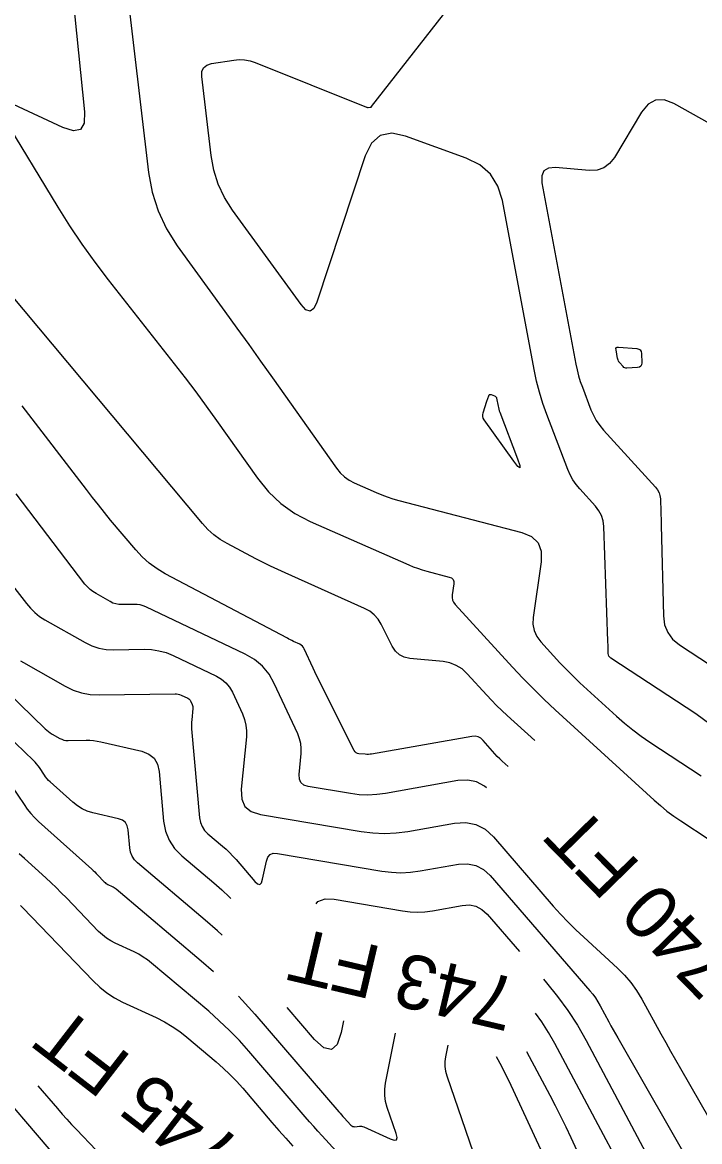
# Model space of a CAD drawing. Extents: x 1354696 to 1366163, y 660729 to 670380.
# Drawn here: x 1361392.2 to 1361467.7, y 664438.2 to 664563.1 of the extents above; entities that cross this region are included whole.
import ezdxf

# ---------------------------------------------------------------- set-up
doc = ezdxf.new("R2010")
doc.units = 0
doc.layers.add('R_Contour Annot', color=7, linetype='Continuous')
doc.layers.add('R_Contours', color=7, linetype='Continuous')

msp = doc.modelspace()

# ---------------------------------------------------------------- linework, layer by layer
at = {"layer": 'R_Contours'}
for points in [[(1361402.78, 664576.02), (1361406.27, 664546.35), (1361406.67, 664544.15), (1361407.34, 664542.05), (1361408.27, 664540.06), (1361409.47, 664538.17), (1361414.8, 664530.82), (1361416.13, 664528.98), (1361417.46, 664527.14), (1361418.77, 664525.29), (1361420.09, 664523.44), (1361427.23, 664513.33), (1361427.65, 664512.82), (1361428.12, 664512.38), (1361428.64, 664512), (1361429.22, 664511.7), (1361431.66, 664510.62), (1361432.27, 664510.37), (1361432.9, 664510.14), (1361433.53, 664509.93), (1361434.17, 664509.75), (1361447.91, 664506.17), (1361448.99, 664505.71), (1361449.72, 664505.02), (1361450.07, 664504.09), (1361450.07, 664502.91), (1361449.18, 664496.69), (1361449.14, 664495.93), (1361449.27, 664495.22), (1361449.57, 664494.57), (1361450.02, 664493.96), (1361452.15, 664491.63), (1361452.69, 664491.05), (1361453.24, 664490.49), (1361453.81, 664489.94), (1361454.38, 664489.4), (1361458.45, 664485.67), (1361459.34, 664484.89), (1361460.26, 664484.15), (1361461.2, 664483.45), (1361462.18, 664482.78), (1361467.9, 664479.01)], [(1361397.16, 664572.51), (1361399.15, 664553.09), (1361399.11, 664551.85), (1361398.69, 664551.15), (1361397.89, 664550.99), (1361396.71, 664551.36), (1361391.22, 664553.92)], [(1361468.87, 664484.79), (1361467.31, 664485.92), (1361457.82, 664492.16), (1361457.7, 664492.26), (1361457.61, 664492.38), (1361457.55, 664492.53), (1361457.53, 664492.68), (1361457.52, 664493.36), (1361457.51, 664493.53), (1361457.51, 664493.7), (1361457.5, 664493.87), (1361457.49, 664494.04), (1361457.03, 664506.84), (1361456.96, 664507.47), (1361456.78, 664508.05), (1361456.5, 664508.6), (1361456.11, 664509.1), (1361454.35, 664511.03), (1361453.94, 664511.52), (1361453.58, 664512.05), (1361453.27, 664512.61), (1361453.01, 664513.2), (1361450.68, 664519.33), (1361450.24, 664520.56), (1361449.86, 664521.81), (1361449.53, 664523.07), (1361449.26, 664524.35), (1361445.74, 664543.2), (1361445.24, 664544.82), (1361444.4, 664546.15), (1361443.22, 664547.2), (1361441.7, 664547.95), (1361434.94, 664550.39), (1361433.39, 664550.71), (1361432.12, 664550.46), (1361431.14, 664549.62), (1361430.43, 664548.2), (1361425.04, 664531.87), (1361424.7, 664531.16), (1361424.29, 664530.88), (1361423.82, 664531.02), (1361423.28, 664531.6), (1361415.63, 664542.14), (1361414.74, 664543.55), (1361414.04, 664545.03), (1361413.55, 664546.59), (1361413.25, 664548.23), (1361412.21, 664557.05), (1361412.23, 664557.6), (1361412.41, 664558.03), (1361412.77, 664558.32), (1361413.3, 664558.49), (1361415.78, 664558.88), (1361416.39, 664558.93), (1361416.99, 664558.91), (1361417.59, 664558.8), (1361418.17, 664558.6), (1361430.59, 664553.62), (1361430.63, 664553.61), (1361430.68, 664553.6), (1361430.73, 664553.59), (1361430.78, 664553.59), (1361430.99, 664553.61), (1361431.04, 664553.62), (1361431.08, 664553.64), (1361431.12, 664553.67), (1361431.15, 664553.7), (1361440.49, 664565.72)], [(1361483.26, 664543.73), (1361464.84, 664554.02), (1361463.77, 664554.44), (1361462.82, 664554.42), (1361461.98, 664553.96), (1361461.26, 664553.07), (1361458.23, 664548.02), (1361457.69, 664547.33), (1361457.04, 664546.85), (1361456.28, 664546.6), (1361455.4, 664546.57), (1361451.66, 664546.88), (1361450.87, 664546.83), (1361450.35, 664546.53), (1361450.11, 664545.98), (1361450.14, 664545.19), (1361453.92, 664524.96), (1361454.06, 664524.31), (1361454.23, 664523.65), (1361454.42, 664523.01), (1361454.65, 664522.38), (1361455.61, 664519.85), (1361455.88, 664519.24), (1361456.2, 664518.66), (1361456.58, 664518.11), (1361457, 664517.59), (1361462.82, 664511.21), (1361463.04, 664510.92), (1361463.2, 664510.61), (1361463.3, 664510.28), (1361463.35, 664509.93), (1361463.4, 664508.45), (1361463.41, 664508.09), (1361463.42, 664507.72), (1361463.44, 664507.35), (1361463.45, 664506.98), (1361463.69, 664496.85), (1361463.82, 664495.88), (1361464.16, 664495.02), (1361464.71, 664494.27), (1361465.47, 664493.65), (1361468.93, 664491.37)], [(1361390.04, 664552.6), (1361396.15, 664542.48), (1361397.46, 664540.38), (1361398.83, 664538.33), (1361400.27, 664536.32), (1361401.77, 664534.36), (1361409.14, 664525), (1361410.35, 664523.44), (1361411.54, 664521.86), (1361412.71, 664520.27), (1361413.86, 664518.67), (1361418.42, 664512.22), (1361419.64, 664510.71), (1361421.03, 664509.4), (1361422.59, 664508.3), (1361424.31, 664507.4), (1361435.28, 664502.56), (1361435.77, 664502.35), (1361436.27, 664502.17), (1361436.78, 664502), (1361437.29, 664501.85), (1361439.8, 664501.2), (1361440.06, 664501.09), (1361440.23, 664500.93), (1361440.31, 664500.71), (1361440.31, 664500.43), (1361440.13, 664499.21), (1361440.12, 664498.91), (1361440.17, 664498.63), (1361440.29, 664498.38), (1361440.46, 664498.14), (1361446.87, 664491.14), (1361448.02, 664489.91), (1361449.2, 664488.71), (1361450.4, 664487.53), (1361451.63, 664486.38), (1361462.64, 664476.31), (1361463.35, 664475.69), (1361464.08, 664475.09), (1361464.84, 664474.53), (1361465.62, 664473.99), (1361468.78, 664471.91)], [(1361449.34, 664482.94), (1361446.26, 664485.76), (1361445.67, 664486.31), (1361445.09, 664486.87), (1361444.53, 664487.45), (1361443.98, 664488.03), (1361441.81, 664490.41), (1361441.23, 664490.94), (1361440.59, 664491.34), (1361439.88, 664491.61), (1361439.11, 664491.76), (1361435.42, 664492.12), (1361434.79, 664492.25), (1361434.25, 664492.52), (1361433.8, 664492.93), (1361433.45, 664493.47), (1361432.22, 664495.92), (1361431.87, 664496.49), (1361431.45, 664496.97), (1361430.94, 664497.38), (1361430.36, 664497.7), (1361421.51, 664501.65), (1361420.68, 664502.02), (1361419.87, 664502.41), (1361419.05, 664502.82), (1361418.25, 664503.23), (1361415.05, 664504.93), (1361414.27, 664505.38), (1361413.55, 664505.91), (1361412.89, 664506.5), (1361412.28, 664507.16), (1361390.61, 664533.09)], [(1361446.38, 664480.04), (1361445.72, 664480.65), (1361445.43, 664480.92), (1361445.15, 664481.19), (1361444.89, 664481.48), (1361444.62, 664481.77), (1361443.6, 664482.96), (1361443.32, 664483.21), (1361443.02, 664483.37), (1361442.68, 664483.44), (1361442.31, 664483.42), (1361431.14, 664481.44), (1361430.97, 664481.42), (1361430.79, 664481.41), (1361430.62, 664481.4), (1361430.44, 664481.42), (1361429.73, 664481.48), (1361429.57, 664481.52), (1361429.43, 664481.59), (1361429.31, 664481.69), (1361429.22, 664481.84), (1361425.43, 664489.39), (1361425.22, 664489.8), (1361425.02, 664490.21), (1361424.83, 664490.62), (1361424.63, 664491.04), (1361423.64, 664493.18), (1361423.55, 664493.34), (1361423.43, 664493.48), (1361423.29, 664493.6), (1361423.13, 664493.69), (1361422.44, 664494.02), (1361422.27, 664494.1), (1361422.1, 664494.19), (1361421.93, 664494.27), (1361421.76, 664494.36), (1361408.14, 664501.56), (1361407.22, 664502.1), (1361406.36, 664502.73), (1361405.56, 664503.44), (1361404.84, 664504.23), (1361402.05, 664507.56), (1361401.36, 664508.4), (1361400.68, 664509.24), (1361400.01, 664510.09), (1361399.34, 664510.95), (1361392.19, 664520.29)], [(1361443.97, 664477.67), (1361443.75, 664477.87), (1361442.85, 664478.34), (1361441.86, 664478.54), (1361440.77, 664478.48), (1361432.69, 664477.05), (1361431.72, 664476.92), (1361430.74, 664476.87), (1361429.77, 664476.91), (1361428.79, 664477.04), (1361424.09, 664477.83), (1361423.6, 664477.99), (1361423.27, 664478.27), (1361423.09, 664478.66), (1361423.06, 664479.18), (1361423.29, 664481.49), (1361423.31, 664482.06), (1361423.25, 664482.61), (1361423.12, 664483.16), (1361422.91, 664483.69), (1361420.3, 664489.32), (1361419.71, 664490.36), (1361418.97, 664491.25), (1361418.09, 664492), (1361417.05, 664492.6), (1361405.98, 664497.86), (1361405.66, 664497.99), (1361405.34, 664498.08), (1361405.01, 664498.13), (1361404.67, 664498.14), (1361403.29, 664498.12), (1361402.95, 664498.14), (1361402.63, 664498.2), (1361402.31, 664498.3), (1361402.01, 664498.45), (1361400.43, 664499.35), (1361400.08, 664499.57), (1361399.75, 664499.82), (1361399.46, 664500.11), (1361399.19, 664500.42), (1361391.5, 664510.47)], [(1361390.6, 664500.92), (1361392.65, 664498.25), (1361393.1, 664497.72), (1361393.59, 664497.24), (1361394.13, 664496.81), (1361394.72, 664496.44), (1361399.2, 664493.89), (1361399.95, 664493.53), (1361400.73, 664493.27), (1361401.54, 664493.12), (1361402.37, 664493.08), (1361405.77, 664493.14), (1361406.61, 664493.11), (1361407.43, 664492.98), (1361408.23, 664492.76), (1361409.01, 664492.44), (1361413.85, 664490.14), (1361414.42, 664489.81), (1361414.9, 664489.4), (1361415.3, 664488.91), (1361415.63, 664488.35), (1361416.75, 664485.92), (1361416.99, 664485.3), (1361417.14, 664484.67), (1361417.21, 664484.03), (1361417.19, 664483.37), (1361416.61, 664477.51), (1361416.66, 664476.43), (1361417.03, 664475.61), (1361417.73, 664475.03), (1361418.76, 664474.71), (1361429.98, 664472.8), (1361431.28, 664472.64), (1361432.58, 664472.59), (1361433.89, 664472.65), (1361435.19, 664472.82), (1361440.4, 664473.74), (1361441.65, 664473.82), (1361442.78, 664473.59), (1361443.81, 664473.05), (1361444.73, 664472.2), (1361451.4, 664464.49), (1361452.21, 664463.58), (1361453.05, 664462.69), (1361453.91, 664461.83), (1361454.8, 664461), (1361458.57, 664457.55), (1361459.35, 664456.78), (1361460.06, 664455.94), (1361460.7, 664455.06), (1361461.27, 664454.11), (1361463.41, 664450.22), (1361463.95, 664449.25), (1361464.49, 664448.28), (1361465.04, 664447.32), (1361465.59, 664446.35), (1361472.04, 664435.11)], [(1361392, 664491.85), (1361392.32, 664491.66), (1361396.97, 664489.01), (1361397.88, 664488.57), (1361398.81, 664488.26), (1361399.78, 664488.08), (1361400.78, 664488.04), (1361409.23, 664488.18), (1361409.41, 664488.17), (1361409.58, 664488.14), (1361409.74, 664488.1), (1361409.9, 664488.03), (1361410.65, 664487.67), (1361410.75, 664487.62), (1361410.83, 664487.55), (1361410.9, 664487.47), (1361410.95, 664487.38), (1361411.14, 664486.97), (1361411.18, 664486.87), (1361411.2, 664486.76), (1361411.21, 664486.65), (1361411.21, 664486.54), (1361411.09, 664485.26), (1361411.07, 664485.01), (1361411.06, 664484.76), (1361411.06, 664484.51), (1361411.08, 664484.26), (1361411.96, 664474.33), (1361412.06, 664473.82), (1361412.24, 664473.35), (1361412.52, 664472.93), (1361412.88, 664472.56), (1361414.52, 664471.18), (1361414.92, 664470.82), (1361415.31, 664470.45), (1361415.68, 664470.07), (1361416.04, 664469.67), (1361418.12, 664467.24), (1361418.43, 664466.96), (1361418.68, 664466.9), (1361418.87, 664467.07), (1361419, 664467.47), (1361419.41, 664469.51), (1361419.56, 664469.94), (1361419.82, 664470.23), (1361420.18, 664470.37), (1361420.64, 664470.36), (1361432.29, 664468.38), (1361433.36, 664468.25), (1361434.42, 664468.2), (1361435.49, 664468.25), (1361436.56, 664468.4), (1361440.83, 664469.15), (1361441.85, 664469.21), (1361442.78, 664469.02), (1361443.63, 664468.58), (1361444.38, 664467.89), (1361455.49, 664455.03), (1361455.82, 664454.64), (1361456.11, 664454.23), (1361456.39, 664453.8), (1361456.64, 664453.36), (1361457.6, 664451.56), (1361457.84, 664451.11), (1361458.08, 664450.66), (1361458.33, 664450.22), (1361458.59, 664449.78), (1361467.26, 664434.66)], [(1361389.1, 664489.71), (1361394.75, 664484.26), (1361394.93, 664484.1), (1361395.12, 664483.95), (1361395.32, 664483.81), (1361395.53, 664483.68), (1361396.38, 664483.19), (1361396.6, 664483.09), (1361396.83, 664483.01), (1361397.06, 664482.97), (1361397.31, 664482.96), (1361399.31, 664482.99), (1361399.72, 664482.98), (1361400.13, 664482.95), (1361400.54, 664482.9), (1361400.95, 664482.81), (1361405.51, 664481.75), (1361406.31, 664481.45), (1361406.9, 664480.97), (1361407.28, 664480.32), (1361407.47, 664479.49), (1361407.96, 664473.95), (1361408.16, 664472.83), (1361408.57, 664471.82), (1361409.17, 664470.9), (1361409.97, 664470.09), (1361413.56, 664467.06), (1361414.44, 664466.28), (1361415.29, 664465.47), (1361415.44, 664465.32)], [(1361414.48, 664461.24), (1361413.96, 664461.73), (1361412.59, 664462.93), (1361405.05, 664469.31), (1361404.71, 664469.66), (1361404.45, 664470.05), (1361404.28, 664470.49), (1361404.19, 664470.97), (1361404.01, 664472.99), (1361403.91, 664473.45), (1361403.69, 664473.8), (1361403.37, 664474.07), (1361402.93, 664474.23), (1361400.06, 664474.9), (1361399.45, 664475.09), (1361398.87, 664475.34), (1361398.34, 664475.67), (1361397.83, 664476.07), (1361395.32, 664478.33), (1361395.13, 664478.51), (1361394.96, 664478.69), (1361394.8, 664478.89), (1361394.66, 664479.1), (1361394.1, 664479.95), (1361393.95, 664480.15), (1361393.79, 664480.35), (1361393.63, 664480.54), (1361393.45, 664480.73), (1361388.41, 664485.58)], [(1361391.01, 664477.91), (1361392.4, 664475.81), (1361392.76, 664475.3), (1361393.15, 664474.81), (1361393.57, 664474.35), (1361394.02, 664473.92), (1361399.94, 664468.59), (1361400.11, 664468.44), (1361400.27, 664468.29), (1361400.43, 664468.13), (1361400.59, 664467.97), (1361401.33, 664467.19), (1361401.43, 664467.1), (1361401.53, 664467.02), (1361401.64, 664466.95), (1361401.75, 664466.89), (1361402.22, 664466.67), (1361402.34, 664466.62), (1361402.45, 664466.55), (1361402.56, 664466.48), (1361402.66, 664466.4), (1361412.15, 664458.37), (1361413.52, 664457.17)], [(1361427.98, 664436.3), (1361425.64, 664438.83), (1361425.16, 664439.36), (1361424.69, 664439.88), (1361424.22, 664440.41), (1361423.75, 664440.95), (1361417.46, 664448.29), (1361416.4, 664449.47), (1361415.31, 664450.6), (1361414.16, 664451.69), (1361412.98, 664452.74), (1361406.61, 664458.12), (1361406.16, 664458.48), (1361405.68, 664458.8), (1361405.19, 664459.1), (1361404.67, 664459.36), (1361402.57, 664460.34), (1361402.06, 664460.6), (1361401.58, 664460.91), (1361401.13, 664461.27), (1361400.71, 664461.66), (1361397.11, 664465.41), (1361396.55, 664465.98), (1361395.98, 664466.54), (1361395.4, 664467.09), (1361394.81, 664467.64), (1361392.43, 664469.78), (1361391.86, 664470.33)], [(1361392, 664464.55), (1361392.27, 664464.27), (1361400.09, 664456.13), (1361400.83, 664455.43), (1361401.63, 664454.8), (1361402.48, 664454.25), (1361403.39, 664453.78), (1361407.12, 664452.04), (1361408.04, 664451.58), (1361408.91, 664451.06), (1361409.75, 664450.48), (1361410.56, 664449.84), (1361413.8, 664447.1), (1361414.59, 664446.41), (1361415.35, 664445.68), (1361416.08, 664444.93), (1361416.78, 664444.15), (1361420.03, 664440.35), (1361420.81, 664439.46), (1361421.59, 664438.57), (1361422.38, 664437.69)], [(1361424.95, 664464.74), (1361425.17, 664464.98), (1361425.96, 664465.28), (1361426.97, 664465.25), (1361434.6, 664463.96), (1361435.43, 664463.85), (1361436.27, 664463.82), (1361437.1, 664463.86), (1361437.93, 664463.97), (1361441.26, 664464.56), (1361442.06, 664464.61), (1361442.78, 664464.46), (1361443.44, 664464.12), (1361444.03, 664463.58), (1361447.64, 664459.4)], [(1361450.3, 664456.32), (1361450.64, 664455.93), (1361451.88, 664454.41), (1361453.03, 664452.83), (1361454.09, 664451.18), (1361455.06, 664449.48), (1361464.27, 664432.19)], [(1361416.3, 664454.44), (1361416.73, 664454), (1361418.14, 664452.43), (1361427.48, 664441.53), (1361427.63, 664441.36), (1361427.78, 664441.19), (1361427.94, 664441.02), (1361428.09, 664440.85), (1361428.84, 664440.04), (1361428.94, 664439.96), (1361429.04, 664439.9), (1361429.15, 664439.88), (1361429.27, 664439.87), (1361429.78, 664439.92), (1361429.91, 664439.93), (1361430.03, 664439.91), (1361430.15, 664439.88), (1361430.27, 664439.84), (1361433.22, 664438.5), (1361433.66, 664438.35), (1361433.92, 664438.41), (1361434, 664438.66), (1361433.9, 664439.11), (1361432.9, 664442.01), (1361432.71, 664442.68), (1361432.62, 664443.35), (1361432.62, 664444.04), (1361432.71, 664444.72), (1361433.83, 664450.32)], [(1361428.02, 664451.69), (1361427.76, 664450.39), (1361427.32, 664449.05), (1361426.67, 664448.47), (1361425.83, 664448.66), (1361424.78, 664449.61), (1361421.73, 664453.17)], [(1361457.85, 664437.37), (1361457.3, 664438.41), (1361451.59, 664449.15), (1361450.89, 664450.37), (1361450.13, 664451.55), (1361449.41, 664452.54)], [(1361439.64, 664448.95), (1361439.39, 664447.67), (1361439.31, 664447.13), (1361439.31, 664446.59), (1361439.39, 664446.06), (1361439.53, 664445.53), (1361443.71, 664433.43)], [(1361448.41, 664448.27), (1361451.01, 664443.38), (1361451.62, 664442.22), (1361452.22, 664441.04), (1361452.79, 664439.87), (1361453.35, 664438.68), (1361457.84, 664429)], [(1361454.03, 664428.66), (1361446.47, 664444.95), (1361446.28, 664445.37), (1361446.07, 664445.78), (1361445.87, 664446.19), (1361445.66, 664446.59), (1361445.08, 664447.67)], [(1361393.93, 664444.44), (1361396.12, 664441.88), (1361396.64, 664441.28), (1361397.16, 664440.69), (1361397.7, 664440.11), (1361398.24, 664439.54), (1361400.43, 664437.26), (1361401, 664436.72), (1361401.61, 664436.23), (1361402.27, 664435.81), (1361402.96, 664435.45), (1361406.56, 664433.77), (1361407.37, 664433.4), (1361408.18, 664433.04), (1361409, 664432.69), (1361409.26, 664432.58)], [(1361401.27, 664430.29), (1361390.2, 664443.24)]]:
    msp.add_lwpolyline(points, dxfattribs=at)
for points in [[(1361458.61, 664525.46), (1361458.6, 664525.5), (1361458.59, 664525.54), (1361458.58, 664525.58), (1361458.4, 664526.54), (1361458.39, 664526.69), (1361458.44, 664526.8), (1361458.54, 664526.85), (1361458.69, 664526.86), (1361460.72, 664526.69), (1361460.94, 664526.64), (1361461.11, 664526.53), (1361461.21, 664526.36), (1361461.25, 664526.14), (1361461.29, 664525.09), (1361461.26, 664524.87), (1361461.18, 664524.72), (1361461.03, 664524.62), (1361460.81, 664524.57), (1361459.59, 664524.51), (1361459.48, 664524.51), (1361459.37, 664524.54), (1361459.28, 664524.59), (1361459.19, 664524.67), (1361458.77, 664525.14), (1361458.74, 664525.17), (1361458.72, 664525.2), (1361458.7, 664525.23), (1361458.68, 664525.27), (1361458.63, 664525.42)], [(1361443.58, 664519.52), (1361444.01, 664520.81), (1361444.21, 664521.43), (1361444.25, 664521.51), (1361444.31, 664521.56), (1361444.38, 664521.57), (1361444.47, 664521.55), (1361444.86, 664521.41), (1361444.94, 664521.37), (1361445.01, 664521.31), (1361445.06, 664521.24), (1361445.09, 664521.14), (1361445.25, 664520.28), (1361445.29, 664520.1), (1361445.33, 664519.92), (1361445.38, 664519.75), (1361445.45, 664519.58), (1361447.43, 664514.37), (1361447.67, 664513.66), (1361447.68, 664513.38), (1361447.45, 664513.54), (1361446.99, 664514.13), (1361443.7, 664518.73), (1361443.6, 664518.91), (1361443.54, 664519.11), (1361443.54, 664519.31)]]:
    msp.add_lwpolyline(points, close=True, dxfattribs=at)

# ---------------------------------------------------------------- texts
at = {"layer": 'R_Contour Annot'}
for s, rotation, p in [('740 FT', 134.3974, (1361472.24, 664457.92)), ('743 FT', 166.7568, (1361447.66, 664456.31)), ('745 FT', 142.2793, (1361416.93, 664438.03))]:
    msp.add_text(s, height=6, rotation=rotation, dxfattribs=at).set_placement(p)

doc.saveas('drawing.dxf')
